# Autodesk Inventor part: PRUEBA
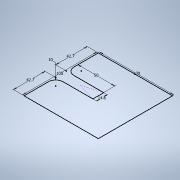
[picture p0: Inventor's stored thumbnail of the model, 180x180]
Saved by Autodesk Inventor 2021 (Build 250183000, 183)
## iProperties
Created: 2021-03
Part Number: PRUEBA
Material: Genérico
Document SubType Name: Modeling
Designer: ucsm
Density: 1 g/cm^3
Appearance: Valor por defecto
Author: ucsm
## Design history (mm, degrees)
sketch "Boceto1"
  geometry: L1 (0, 0)-(100, 0); L2 (100, -100)-(0, -100); L3 (0, -100)-(0, 0); L4 (90, -42.7)-(50, -42.7); L5 (50, -42.7)-(50, -57.3); L6 (50, -57.3)-(90, -57.3); L7 (75, -50)-(50, -57.3); L8 (50, -42.7)-(75, -50); L9 (100, 0)-(100, -32.7); L10 (100, -67.3)-(100, -100); A1 r 10 centre (90, -32.7) between (90, -42.7) and (100, -32.7); A2 r 10 centre (90, -67.3) between (100, -67.3) and (90, -57.3); 2 further points
  constraints: 20 end point, 4 parallel, 4 point on circle, 4 point on line, 4 tangent, 3 perpendicular, 2 centre point, 2 horizontal, 1 equal radius
  dimensions: "d0" = 100 distance of L2.start L2.end; "d1" = 100 distance of L1.end L2.start; "d3" = 14.6 distance of L5.end L4.end; "d4" = 42.7 distance of L1.end point (100, -42.7); "d5" = 42.7 distance of L2.start point (100, -57.3); "d6" = 10 radius of A1 (derived); "d7" = 50 distance from line of L10 L5.end
